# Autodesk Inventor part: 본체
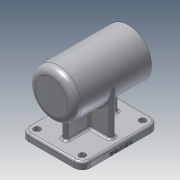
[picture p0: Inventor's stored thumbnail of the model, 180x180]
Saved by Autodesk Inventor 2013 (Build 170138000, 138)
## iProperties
Created: 2020-10
Part Number: 본체
Material: 알루미늄 6061
Document SubType Name: Modeling
Designer: 88
Density: 2.71 g/cm^3
Mass: 1030.08 g
Surface Area: 757.984 cm^2
Volume: 380.102 cm^3
Author: 88
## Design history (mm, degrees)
sketch "스케치1"
  geometry: C1 r 34 at (0, 0); 1 further point
  constraints: 1 centre point, 1 coincident
  dimensions: "d0" = 68 diameter of C1
extrude "돌출1" new body sketch "스케치1" stored distance "d1" = 112; taper "d2" = 0 deg
sketch "스케치2"
  geometry: L1 (34, -56)-(-34, -56) reference; L2 (-34, -56)-(-34, 56) reference; L3 (-34, 56)-(34, 56) reference; L4 (34, 56)-(34, -56) reference; L5 (0, -56)-(0, 56); L6 (0, -56)-(21, -56); L7 (21, -56)-(21, -41); L8 (21, -41)-(24, -41); L9 (24, -41)-(24, 13); L10 (24, 13)-(21, 13); L11 (21, 13)-(21, 25); L12 (21, 25)-(17.5, 25); L13 (17.5, 25)-(17.5, 43); L14 (17.5, 43)-(16, 43); L15 (16, 43)-(16, 47); L16 (16, 47)-(10.5, 47); L17 (10.5, 47)-(10.5, 50); L18 (10.5, 50)-(0, 50); 1 further point
  constraints: 28 end point, 8 parallel, 4 perpendicular, 2 midpoint, 2 point on line
  dimensions: "d3" = 42 diameter of L7 L5; "d5" = 48 diameter of L9 L5; "d6" = 15 distance of L6.end L7.end; "d7" = 42 diameter of L11 L5; "d8" = 54 distance of L8.end L9.end; "d9" = 12 distance of L10.end L11.end; "d10" = 35 diameter of L13 L5; "d11" = 18 distance of L12.end L13.end; "d12" = 32 diameter of L15 L5; "d13" = 4 distance of L14.end L15.end; "d14" = 21 diameter of L17 L5; "d15" = 3 distance of L16.end L17.end
revolve "회전1" sketch "스케치2" stored, may be unused: angle "d16" = 90 deg
node "작업 평면1"
sketch "스케치3"
  geometry: L1 (45, -56)-(-45, -56); L2 (-45, -56)-(-45, 56); L3 (-45, 56)-(45, 56); L4 (45, 56)-(45, -56); L5 (45, -56)-(-45, 56); L6 (-45, -56)-(45, 56); 1 further point
  constraints: 12 end point, 2 midpoint, 2 parallel, 1 horizontal, 1 perpendicular
  dimensions: "d18" = 90 distance of L2.end L3.end; "d19" = 112 distance of L1.end L2.end
extrude "돌출2" join sketch "스케치3" distance "d20" = 10; taper "d21" = 0 deg
sketch "스케치4"
  geometry: L1 (-4, -38)-(4, -38); L2 (4, -38)-(4, 38); L3 (4, 38)-(-4, 38); L4 (-4, 38)-(-4, -38); L5 (-4, -38)-(4, 38); L6 (4, -38)-(-4, 38); L7 (34, -4)-(-34, -4); L8 (-34, -4)-(-34, 4); L9 (-34, 4)-(34, 4); L10 (34, 4)-(34, -4); L11 (34, -4)-(-34, 4); L12 (-34, -4)-(34, 4); 1 further point
  constraints: 24 end point, 4 midpoint, 4 parallel, 2 horizontal, 2 perpendicular
  dimensions: "d22" = 8 distance of L2.end L3.end; "d24" = 76 distance of L1.end L2.end; "d25" = 68 distance of L8.end L9.end; "d26" = 8 distance of L7.end L8.end
extrude "돌출3" join sketch "스케치4" stored distance "d27" = 0; taper "d28" = 0 deg
sketch "스케치5" dims "d29" = 52
  geometry: C1 r 21 at (0, 0) reference; C2 r 34 at (0, 0) reference; 2 further points
  constraints: 2 vertical alignment, 1 coincident, 2 other
hole "구멍1" sketch "스케치5" at (0, 26) diameter "d30" = 3.242; stored, may be unused: countersink angle "d34" = 90 deg, drill point angle "d36" = 118 deg; dims "d31" = 8, "d32" = 4, "d33" = 2, "d35" = 11
fillet "모깎기1" dims "d40" = 12
sketch "스케치6"
  geometry: A1 r 12 centre (-33, 44) between (-33, 56) and (-45, 44) reference; A2 r 12 centre (-33, -44) between (-45, -44) and (-33, -56) reference; A3 r 12 centre (33, -44) between (33, -56) and (45, -44) reference; A4 r 12 centre (33, 44) between (45, 44) and (33, 56) reference; 5 further points
  constraints: 4 coincident
hole "구멍2" sketch "스케치6" at (-33, 44), (33, 44), (33, -44), (-33, -44) diameter "d41" = 5.5; stored, may be unused: countersink angle "d45" = 90 deg, drill point angle "d47" = 118 deg; dims "d42" = 8, "d43" = 9.5, "d44" = 5.4, "d46" = 11
sketch "스케치7"
  geometry: L1 (88, 0)-(0, 0) reference; L2 (100, 0)-(100, 10) reference; 2 further points
  constraints: 1 other
  dimensions: "d48" = 56 distance from line of L2 point (44, 3); "d49" = 3 distance from line of L1 point (44, 3)
feature "엠보싱1" sketch "스케치7" dims "d16" = 90 deg, "d50" = 0.5, "d51" = 0
fillet "모깎기2" dims "d52" = 3
fillet "모깎기3" dims "d53" = 10
fillet "모깎기4" dims "d54" = 3
fillet "모깎기5" dims "d55" = 3
fillet "모깎기6" dims "d56" = 0.3
fillet "모깎기7" dims "d57" = 3
fillet "모깎기8" dims "d58" = 3
chamfer "모따기1" distance "d59" = 1; stored, may be unused: second distance "d60" = 2, angle "d61" = 45 deg
node "솔리드1"
pattern_circular "원형 패턴1" dims angle "d38" = 360 deg
node "절단 모서리 투영1"
other parameters: "d17" = -74
